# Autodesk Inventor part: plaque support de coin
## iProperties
Shininess: 64.0
Length Units: 11269
Angle Units: 11279
Time Units: 11290
Mass Units: 11283
Length Display Precision: 3
Angle Display Precision: 2
Compacted: True
Part Number: plaque support de coin
Document SubType Name: Modeling
Created: 2004-12
Material: Par défaut
Designer: LEGERET Philippe
Density: 0.0
Volumn: 0.0
Area: 0.0
PropertySet Name: Model Information
Control State: 0
Master: False
Checked Out: False
Author: LEGERET Philippe
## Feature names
1. Extrusion1
2. Extrusion2
3. Perçage1 [Hole]
4. Perçage2 [Hole]
